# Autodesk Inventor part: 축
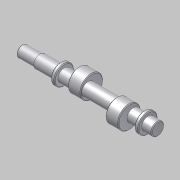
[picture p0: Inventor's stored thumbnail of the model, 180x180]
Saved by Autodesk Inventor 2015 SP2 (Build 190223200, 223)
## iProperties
Created: 2013-02
Part Number: 축
Document SubType Name: Modeling
Designer: 한국산업디자인학원[gmhk.co.kr]
Density: 1 g/cm^3
Material: 일반
Appearance: 기본값
Author: 한국산업디자인학원[gmhk.co.kr]
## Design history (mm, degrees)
sketch "스케치2"
  geometry: L1 (-58, 84.5)-(-58, 15.5) reference; L2 (58, 15.5)-(58, 84.5) reference; L3 (-85, 25.774)-(-85, 74.226) reference; L4 (70, 84.185)-(70, 15.815) reference; L5 (71, 50)-(-109, 50); L6 (69.4, 58.5)-(58.6, 58.5) reference; L7 (71, 50)-(71, 58.5); L8 (71, 58.5)-(58, 58.5); L9 (58, 58.5)-(58, 63); L10 (58, 63)-(53, 63); L11 (53, 63)-(53, 58.5); L12 (53, 58.5)-(-53, 58.5); L13 (-53, 58.5)-(-53, 63); L14 (-53, 63)-(-58, 63); L15 (-58, 63)-(-58, 58.5); L16 (-58, 58.5)-(-85, 58.5); L17 (-85, 58.5)-(-85, 57.5); L18 (-85, 57.5)-(-109, 57.5); L19 (-109, 57.5)-(-109, 50); L20 (-30, 102.5)-(-30, 50); L21 (30, 102.5)-(30, 50); L22 (-50, 102.5)-(-10, 102.5) reference; L23 (10, 102.5)-(50, 102.5) reference; 2 further points
  constraints: 34 end point, 10 perpendicular, 9 point on line, 5 collinear, 3 midpoint, 3 parallel, 1 horizontal, 2 other
  dimensions: "d0" = 1 distance between parallel lines of L7 L4; "d1" = 26 diameter of L10 L5; "d2" = 5 distance of L9.end L10.end; "d3" = 5 distance of L13.end L14.end (= d2); "d4" = 180 distance of L5.start L5.end; "d5" = 15 diameter of L18 L5
  node "참조1"
  node "참조2"
  node "참조3"
  node "참조4"
  node "참조7"
  node "참조8"
revolve "회전1" stored, may be unused: angle "d6" = 90 deg
node "작업 평면1"
sketch "스케치3"
  geometry: C1 r 8.5 at (52.5, 0) reference; C2 r 15 at (47.5, 0); 1 further point
  constraints: 1 centre point, 1 horizontal alignment
  dimensions: "d8" = 5 distance of C1.centre C2.centre; "d9" = 30 diameter of C2
extrude "돌출1" join sketch "스케치3" stored distance "d10" = 17; taper "d11" = 0 deg
node "작업 평면2"
sketch "스케치4"
  geometry: C1 r 8.5 at (52.5, 0) reference; C2 r 15 at (57.5, 0); 1 further point
  constraints: 1 centre point, 1 horizontal alignment
  dimensions: "d13" = 5 distance of C2.centre C1.centre; "d14" = 30 diameter of C2
extrude "돌출2" join sketch "스케치4" stored distance "d15" = 17; taper "d16" = 0 deg
chamfer "모따기1" distance "d17" = 1; stored, may be unused: second distance "d18" = 2, angle "d19" = 45 deg
node "작업 평면3"
sketch "스케치5"
  geometry: L1 (12, 6.5)-(12, -6.5) reference; L2 (12, 2.5)-(-5.5, 2.5); L3 (-5.5, -2.5)-(12, -2.5); A1 r 2.5 centre (-5.5, 0) between (-5.5, 2.5) and (-5.5, -2.5); 2 further points
  constraints: 4 end point, 2 point on circle, 2 point on line, 2 tangent, 1 centre point, 1 horizontal alignment, 1 midpoint, 1 parallel, 1 perpendicular
  dimensions: "d20" = 5 distance between parallel lines of L3 L2; "d21" = 20 dimension on A1 L1
extrude "돌출3" cut sketch "스케치5" distance "d22" = 3; taper "d23" = 0 deg
chamfer "모따기2" distance "d24" = 1; stored, may be unused: second distance "d25" = 2, angle "d26" = 45 deg
node "솔리드1"
node "투영된 루프1"
node "투영된 루프2"
other parameters: "d7" = 0, "d12" = 0
